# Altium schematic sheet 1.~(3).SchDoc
size 420 x 297 mm
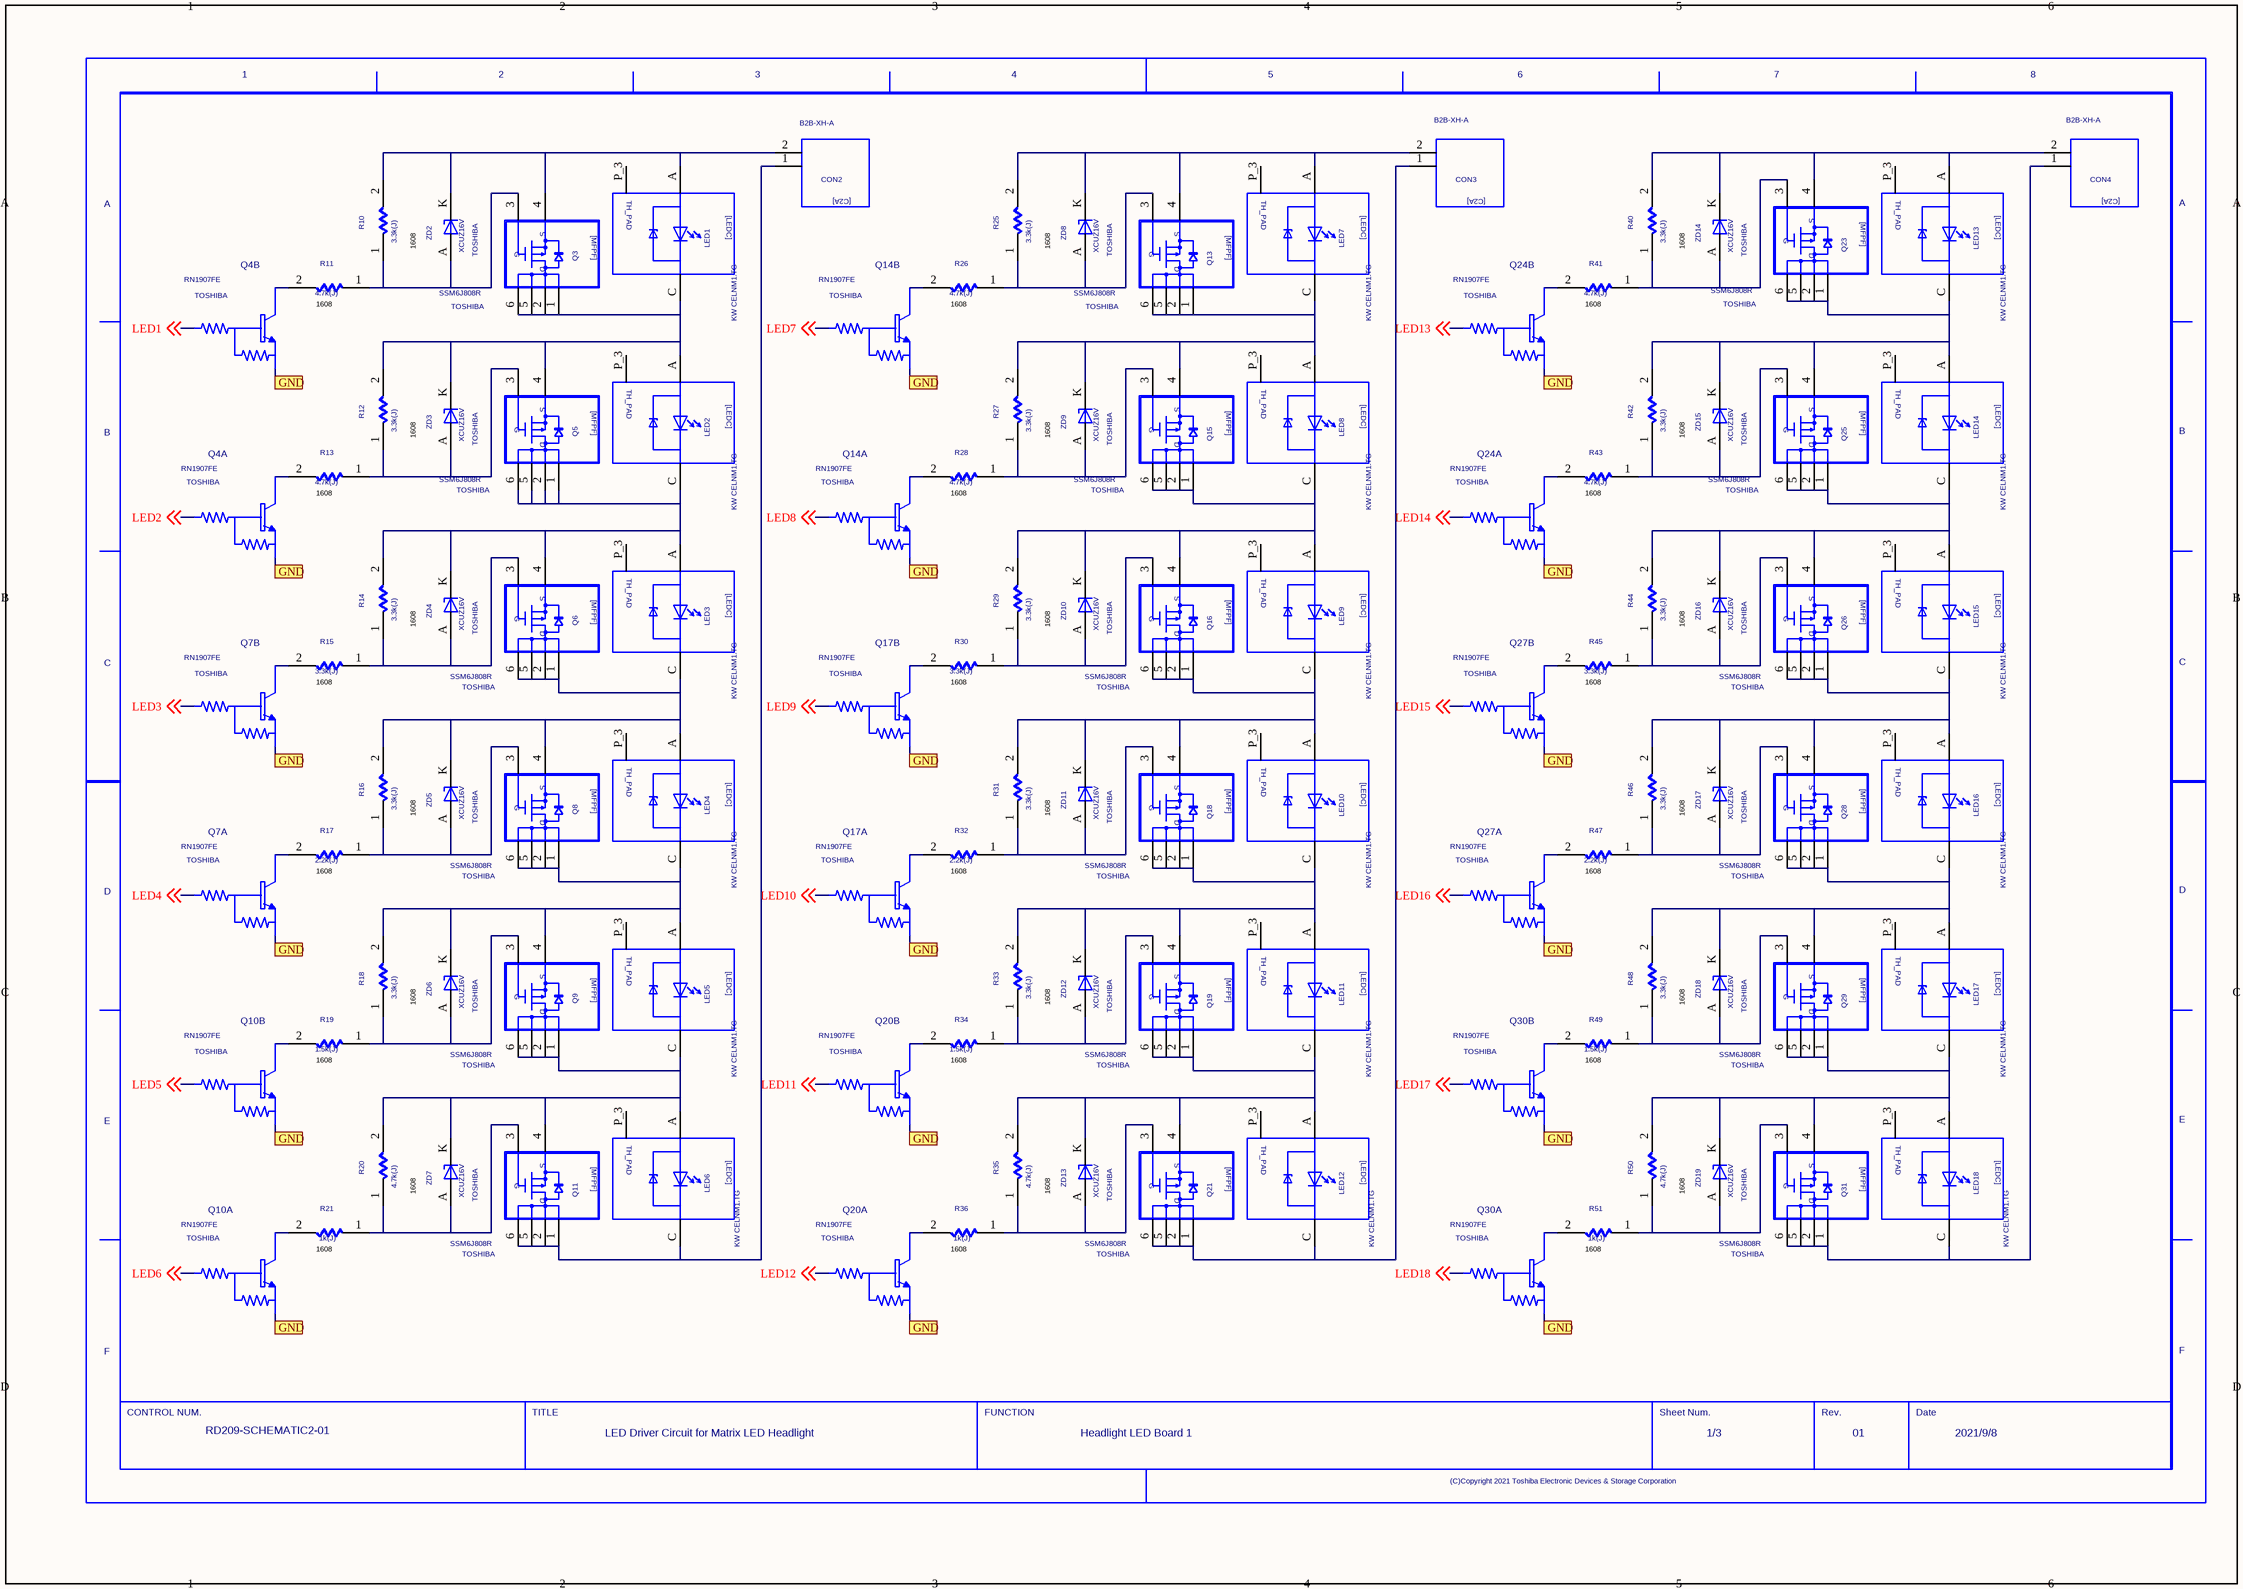
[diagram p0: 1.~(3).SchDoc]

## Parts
CON2  VAL3: B2B-XH-A  (hidden comment: C2A)
CON3  VAL3: B2B-XH-A  (hidden comment: C2A)
CON4  VAL3: B2B-XH-A  (hidden comment: C2A)
LED1  VAL3: KW CELNM1.TG  (hidden comment: LEDC)
LED2  VAL3: KW CELNM1.TG  (hidden comment: LEDC)
LED3  VAL3: KW CELNM1.TG  (hidden comment: LEDC)
LED4  VAL3: KW CELNM1.TG  (hidden comment: LEDC)
LED5  VAL3: KW CELNM1.TG  (hidden comment: LEDC)
LED6  VAL3: KW CELNM1.TG  (hidden comment: LEDC)
LED7  VAL3: KW CELNM1.TG  (hidden comment: LEDC)
LED8  VAL3: KW CELNM1.TG  (hidden comment: LEDC)
LED9  VAL3: KW CELNM1.TG  (hidden comment: LEDC)
LED10  VAL3: KW CELNM1.TG  (hidden comment: LEDC)
LED11  VAL3: KW CELNM1.TG  (hidden comment: LEDC)
LED12  VAL3: KW CELNM1.TG  (hidden comment: LEDC)
LED13  VAL3: KW CELNM1.TG  (hidden comment: LEDC)
LED14  VAL3: KW CELNM1.TG  (hidden comment: LEDC)
LED15  VAL3: KW CELNM1.TG  (hidden comment: LEDC)
LED16  VAL3: KW CELNM1.TG  (hidden comment: LEDC)
LED17  VAL3: KW CELNM1.TG  (hidden comment: LEDC)
LED18  VAL3: KW CELNM1.TG  (hidden comment: LEDC)
Q3  USERCOMPTEXT3: TOSHIBA  VAL3: SSM6J808R  (hidden comment: MFPF)
Q4  USERCOMPTEXT3: TOSHIBA  VAL3: RN1907FE  (hidden comment: RN1907FE_1)  (parts A,B of 2)
Q5  USERCOMPTEXT3: TOSHIBA  VAL3: SSM6J808R  (hidden comment: MFPF)
Q6  USERCOMPTEXT3: TOSHIBA  VAL3: SSM6J808R  (hidden comment: MFPF)
Q7  USERCOMPTEXT3: TOSHIBA  VAL3: RN1907FE  (hidden comment: RN1907FE_1)  (parts A,B of 2)
Q8  USERCOMPTEXT3: TOSHIBA  VAL3: SSM6J808R  (hidden comment: MFPF)
Q9  USERCOMPTEXT3: TOSHIBA  VAL3: SSM6J808R  (hidden comment: MFPF)
Q10  USERCOMPTEXT3: TOSHIBA  VAL3: RN1907FE  (hidden comment: RN1907FE_1)  (parts A,B of 2)
Q11  USERCOMPTEXT3: TOSHIBA  VAL3: SSM6J808R  (hidden comment: MFPF)
Q13  USERCOMPTEXT3: TOSHIBA  VAL3: SSM6J808R  (hidden comment: MFPF)
Q14  USERCOMPTEXT3: TOSHIBA  VAL3: RN1907FE  (hidden comment: RN1907FE_1)  (parts A,B of 2)
Q15  USERCOMPTEXT3: TOSHIBA  VAL3: SSM6J808R  (hidden comment: MFPF)
Q16  USERCOMPTEXT3: TOSHIBA  VAL3: SSM6J808R  (hidden comment: MFPF)
Q17  USERCOMPTEXT3: TOSHIBA  VAL3: RN1907FE  (hidden comment: RN1907FE_1)  (parts A,B of 2)
Q18  USERCOMPTEXT3: TOSHIBA  VAL3: SSM6J808R  (hidden comment: MFPF)
Q19  USERCOMPTEXT3: TOSHIBA  VAL3: SSM6J808R  (hidden comment: MFPF)
Q20  USERCOMPTEXT3: TOSHIBA  VAL3: RN1907FE  (hidden comment: RN1907FE_1)  (parts A,B of 2)
Q21  USERCOMPTEXT3: TOSHIBA  VAL3: SSM6J808R  (hidden comment: MFPF)
Q23  USERCOMPTEXT3: TOSHIBA  VAL3: SSM6J808R  (hidden comment: MFPF)
Q24  USERCOMPTEXT3: TOSHIBA  VAL3: RN1907FE  (hidden comment: RN1907FE_1)  (parts A,B of 2)
Q25  USERCOMPTEXT3: TOSHIBA  VAL3: SSM6J808R  (hidden comment: MFPF)
Q26  USERCOMPTEXT3: TOSHIBA  VAL3: SSM6J808R  (hidden comment: MFPF)
Q27  USERCOMPTEXT3: TOSHIBA  VAL3: RN1907FE  (hidden comment: RN1907FE_1)  (parts A,B of 2)
Q28  USERCOMPTEXT3: TOSHIBA  VAL3: SSM6J808R  (hidden comment: MFPF)
Q29  USERCOMPTEXT3: TOSHIBA  VAL3: SSM6J808R  (hidden comment: MFPF)
Q30  USERCOMPTEXT3: TOSHIBA  VAL3: RN1907FE  (hidden comment: RN1907FE_1)  (parts A,B of 2)
Q31  USERCOMPTEXT3: TOSHIBA  VAL3: SSM6J808R  (hidden comment: MFPF)
R10  VAL1: 3.3k(J)  (hidden comment: R)
R11  VAL1: 4.7k(J)  (hidden comment: R)
R12  VAL1: 3.3k(J)  (hidden comment: R)
R13  VAL1: 4.7k(J)  (hidden comment: R)
R14  VAL1: 3.3k(J)  (hidden comment: R)
R15  VAL1: 3.3k(J)  (hidden comment: R)
R16  VAL1: 3.3k(J)  (hidden comment: R)
R17  VAL1: 2.2k(J)  (hidden comment: R)
R18  VAL1: 3.3k(J)  (hidden comment: R)
R19  VAL1: 1.5k(J)  (hidden comment: R)
R20  VAL1: 4.7k(J)  (hidden comment: R)
R21  VAL1: 1k(J)  (hidden comment: R)
R25  VAL1: 3.3k(J)  (hidden comment: R)
R26  VAL1: 4.7k(J)  (hidden comment: R)
R27  VAL1: 3.3k(J)  (hidden comment: R)
R28  VAL1: 4.7k(J)  (hidden comment: R)
R29  VAL1: 3.3k(J)  (hidden comment: R)
R30  VAL1: 3.3k(J)  (hidden comment: R)
R31  VAL1: 3.3k(J)  (hidden comment: R)
R32  VAL1: 2.2k(J)  (hidden comment: R)
R33  VAL1: 3.3k(J)  (hidden comment: R)
R34  VAL1: 1.5k(J)  (hidden comment: R)
R35  VAL1: 4.7k(J)  (hidden comment: R)
R36  VAL1: 1k(J)  (hidden comment: R)
R40  VAL1: 3.3k(J)  (hidden comment: R)
R41  VAL1: 4.7k(J)  (hidden comment: R)
R42  VAL1: 3.3k(J)  (hidden comment: R)
R43  VAL1: 4.7k(J)  (hidden comment: R)
R44  VAL1: 3.3k(J)  (hidden comment: R)
R45  VAL1: 3.3k(J)  (hidden comment: R)
R46  VAL1: 3.3k(J)  (hidden comment: R)
R47  VAL1: 2.2k(J)  (hidden comment: R)
R48  VAL1: 3.3k(J)  (hidden comment: R)
R49  VAL1: 1.5k(J)  (hidden comment: R)
R50  VAL1: 4.7k(J)  (hidden comment: R)
R51  VAL1: 1k(J)  (hidden comment: R)
U?  DATE: 2021/9/8  REVISION: 01  SHEETNUMBER: 1/3  FUNCTION: Headlight LED Board 1  TITLE: LED Driver Circuit for / Matrix LED Headlight  DRAWINGNUMBER: RD209-SCHEMATIC2-01  (hidden comment: WAKU_DEF100)
ZD2  USERCOMPTEXT3: TOSHIBA  VAL3: XCUZ16V  (hidden comment: ZD)
ZD3  USERCOMPTEXT3: TOSHIBA  VAL3: XCUZ16V  (hidden comment: ZD)
ZD4  USERCOMPTEXT3: TOSHIBA  VAL3: XCUZ16V  (hidden comment: ZD)
ZD5  USERCOMPTEXT3: TOSHIBA  VAL3: XCUZ16V  (hidden comment: ZD)
ZD6  USERCOMPTEXT3: TOSHIBA  VAL3: XCUZ16V  (hidden comment: ZD)
ZD7  USERCOMPTEXT3: TOSHIBA  VAL3: XCUZ16V  (hidden comment: ZD)
ZD8  USERCOMPTEXT3: TOSHIBA  VAL3: XCUZ16V  (hidden comment: ZD)
ZD9  USERCOMPTEXT3: TOSHIBA  VAL3: XCUZ16V  (hidden comment: ZD)
ZD10  USERCOMPTEXT3: TOSHIBA  VAL3: XCUZ16V  (hidden comment: ZD)
ZD11  USERCOMPTEXT3: TOSHIBA  VAL3: XCUZ16V  (hidden comment: ZD)
ZD12  USERCOMPTEXT3: TOSHIBA  VAL3: XCUZ16V  (hidden comment: ZD)
ZD13  USERCOMPTEXT3: TOSHIBA  VAL3: XCUZ16V  (hidden comment: ZD)
ZD14  USERCOMPTEXT3: TOSHIBA  VAL3: XCUZ16V  (hidden comment: ZD)
ZD15  USERCOMPTEXT3: TOSHIBA  VAL3: XCUZ16V  (hidden comment: ZD)
ZD16  USERCOMPTEXT3: TOSHIBA  VAL3: XCUZ16V  (hidden comment: ZD)
ZD17  USERCOMPTEXT3: TOSHIBA  VAL3: XCUZ16V  (hidden comment: ZD)
ZD18  USERCOMPTEXT3: TOSHIBA  VAL3: XCUZ16V  (hidden comment: ZD)
ZD19  USERCOMPTEXT3: TOSHIBA  VAL3: XCUZ16V  (hidden comment: ZD)

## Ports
GND

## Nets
LED2: Q4.2 ; off-sheet LED2
LED3: Q7.5 ; off-sheet LED3
LED4: Q7.2 ; off-sheet LED4
LED5: Q10.5 ; off-sheet LED5
LED6: Q10.2 ; off-sheet LED6
LED7: Q14.5 ; off-sheet LED7
LED8: Q14.2 ; off-sheet LED8
LED9: Q17.5 ; off-sheet LED9
LED10: Q17.2 ; off-sheet LED10
LED11: Q20.5 ; off-sheet LED11
LED12: Q20.2 ; off-sheet LED12
LED13: Q24.5 ; off-sheet LED13
LED14: Q24.2 ; off-sheet LED14
LED15: Q27.5 ; off-sheet LED15
LED16: Q27.2 ; off-sheet LED16
LED17: Q30.5 ; off-sheet LED17
LED18: Q30.2 ; off-sheet LED18
LED+1: CON2.2 LED1.A Q3.4 R10.2 ZD2.K(C)
LED+2: CON3.2 LED7.A Q13.4 R25.2 ZD8.K(C)
LED+3: CON4.2 LED13.A Q23.4 R40.2 ZD14.K(C)
LED-1: CON2.1 LED6.C Q11.1 Q11.2 Q11.5 Q11.6
LED-2: CON3.1 LED12.C Q21.1 Q21.2 Q21.5 Q21.6
SIG1: Q4.5 ; off-sheet LED1  [also labelled LED1]
SIG2: Q4.3 R11.2
SIG3: Q3.3 R10.1 R11.1 ZD2.A
SIG6: Q5.3 R12.1 R13.1 ZD3.A
SIG7: Q4.6 R13.2
SIG10: Q7.6 R17.2
SIG11: Q8.3 R16.1 R17.1 ZD5.A
SIG12: Q4.1 Q4.4 Q7.1 Q7.4 Q10.1 Q10.4 Q14.1 Q14.4 Q17.1 Q17.4 Q20.1 Q20.4 Q24.1 Q24.4 Q27.1 Q27.4 Q30.1 Q30.4 ; port GND  [also labelled SIG18, SIG21, SIG26, SIG30, SIG34, SIG35, SIG40, SIG45, SIG51, SIG54, SIG59, SIG60, SIG66, SIG72, SIG74, SIG8]
SIG15: LED3.C LED4.A Q6.1 Q6.2 Q6.5 Q6.6 Q8.4 R16.2 ZD5.K(C)
SIG16: Q6.3 R14.1 R15.1 ZD4.A
SIG17: Q7.3 R15.2
SIG19: Q10.6 R21.2
SIG20: Q11.3 R20.1 R21.1 ZD7.A
SIG23: LED5.C LED6.A Q9.1 Q9.2 Q9.5 Q9.6 Q11.4 R20.2 ZD7.K(C)
SIG24: Q9.3 R18.1 R19.1 ZD6.A
SIG25: Q10.3 R19.2
SIG28: LED2.C LED3.A Q5.1 Q5.2 Q5.5 Q5.6 Q6.4 R14.2 ZD4.K(C)
SIG29: Q20.3 R34.2
SIG32: Q13.3 R25.1 R26.1 ZD8.A
SIG33: Q14.3 R26.2
SIG36: Q21.3 R35.1 R36.1 ZD13.A
SIG37: Q20.6 R36.2
SIG38: Q17.3 R30.2
SIG39: LED9.C LED10.A Q16.1 Q16.2 Q16.5 Q16.6 Q18.4 R31.2 ZD11.K(C)
SIG42: LED8.C LED9.A Q15.1 Q15.2 Q15.5 Q15.6 Q16.4 R29.2 ZD10.K(C)
SIG43: LED10.C LED11.A Q18.1 Q18.2 Q18.5 Q18.6 Q19.4 R33.2 ZD12.K(C)
SIG44: LED7.C LED8.A Q13.1 Q13.2 Q13.5 Q13.6 Q15.4 R27.2 ZD9.K(C)
SIG46: Q17.6 R32.2
SIG47: LED11.C LED12.A Q19.1 Q19.2 Q19.5 Q19.6 Q21.4 R35.2 ZD13.K(C)
SIG48: Q16.3 R29.1 R30.1 ZD10.A
SIG49: Q18.3 R31.1 R32.1 ZD11.A
SIG50: Q15.3 R27.1 R28.1 ZD9.A
SIG52: Q14.6 R28.2
SIG55: Q27.3 R45.2
SIG57: LED15.C LED16.A Q26.1 Q26.2 Q26.5 Q26.6 Q28.4 R46.2 ZD17.K(C)
SIG58: LED14.C LED15.A Q25.1 Q25.2 Q25.5 Q25.6 Q26.4 R44.2 ZD16.K(C)
SIG61: Q29.3 R48.1 R49.1 ZD18.A
SIG62: Q24.3 R41.2
SIG63: Q31.3 R50.1 R51.1 ZD19.A
SIG64: Q23.3 R40.1 R41.1 ZD14.A
SIG65: Q30.6 R51.2
SIG67: Q30.3 R49.2
SIG69: Q24.6 R43.2
SIG71: Q28.3 R46.1 R47.1 ZD17.A
SIG73: LED13.C LED14.A Q23.1 Q23.2 Q23.5 Q23.6 Q25.4 R42.2 ZD15.K(C)
SIG75: Q26.3 R44.1 R45.1 ZD16.A
SIG76: LED16.C LED17.A Q28.1 Q28.2 Q28.5 Q28.6 Q29.4 R48.2 ZD18.K(C)
SIG77: LED17.C LED18.A Q29.1 Q29.2 Q29.5 Q29.6 Q31.4 R50.2 ZD19.K(C)
SIG78: Q27.6 R47.2
SIG214: LED1.C LED2.A Q3.1 Q3.2 Q3.5 Q3.6 Q5.4 R12.2 ZD3.K(C)
SIG215: LED4.C LED5.A Q8.1 Q8.2 Q8.5 Q8.6 Q9.4 R18.2 ZD6.K(C)
SIG216: Q19.3 R33.1 R34.1 ZD12.A
SIG217: Q25.3 R42.1 R43.1 ZD15.A
SIG218: CON4.1 LED18.C Q31.1 Q31.2 Q31.5 Q31.6

Not connected (* = marked no-connect by the designer): LED1 P_3(NC); LED2 P_3(NC); LED3 P_3(NC); LED4 P_3(NC); LED5 P_3(NC); LED6 P_3(NC); LED7 P_3(NC); LED8 P_3(NC); LED9 P_3(NC); LED10 P_3(NC); LED11 P_3(NC); LED12 P_3(NC); LED13 P_3(NC); LED14 P_3(NC); LED15 P_3(NC); LED16 P_3(NC); LED17 P_3(NC); LED18 P_3(NC)

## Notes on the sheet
- 1608
- (near R11) 1608
- (near R26) 1608
- (near R41) 1608
- (near R13) 1608
- (near R28) 1608
- (near R43) 1608
- (near R15) 1608
- (near R30) 1608
- (near R45) 1608
- (near R17) 1608
- (near R32) 1608
- (near R47) 1608
- (near R19) 1608
- (near R34) 1608
- (near R49) 1608
- (near R21) 1608
- (near R36) 1608
- (near R51) 1608

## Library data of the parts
CON2-CON4 = C2A: SAVEAREA0: -4611,-206,24632,18258; SAVECOUNT: 25; TIME: 13:28:28; UPDATEUSER: tomizawa-y; UPDATETIME: 12:08:31; OriginalSymbolOrigin: (2540,15240)
LED1-LED18 = LEDC: SAVEAREA0: -10936,-329,35896,28705; TIME: 14:49:55; UPDATEUSER: fukuda-y; UPDATETIME: 15:53:51; SAVECOUNT: 15; OriginalSymbolOrigin: (5080,25400); COMPONENTNAME: LED; CDBNAME: KW
Q3 Q5 Q6 Q8 Q9 Q11 Q13 Q15 Q16 Q18 Q19 Q21 Q23 Q25 Q26 Q28 Q29 Q31 = MFPF: SAVECOUNT: 11; SAVEAREA0: -6011,0,28984,22860; OriginalSymbolOrigin: (5080,20320); COMPONENTNAME: TSOP6F
Q4 Q7 Q10 Q14 Q17 Q20 Q24 Q27 Q30 = RN1907FE_1: COMP: ES6; TIME: 08:46:53; UPDATEUSER: t5459927; UPDATETIME: 14:30:50; SAVECOUNT: 6; SAVEAREA0: -3836,-13019,18528,3377; OriginalSymbolOrigin: (0,5080); CaptureCellPackProp: RN1907FE_1A
R10 R19 R25 R34 R40 R49 = R: OriginalSymbolOrigin: (5080,5080); COMPONENTNAME: R0603_1; VAL2: 100mW
R11 R18 R26 R33 R41 R48 = R: OriginalSymbolOrigin: (5080,5080); COMPONENTNAME: R0603_2; VAL2: 100mW
R12 R27 R42 = R: OriginalSymbolOrigin: (5080,5080); VAL2: 100mW; COMPONENTNAME: R0603_3
R13 R15 R28 R30 R43 R45 = R: OriginalSymbolOrigin: (5080,5080); COMPONENTNAME: R0603_4; VAL2: 100mW
R14 R17 R29 R32 R44 R47 = R: OriginalSymbolOrigin: (5080,5080); COMPONENTNAME: R0603_5; VAL2: 100mW
R16 R31 R46 = R: OriginalSymbolOrigin: (5080,5080); VAL2: 100mW; COMPONENTNAME: R0603_6
R20 R35 R50 = R: OriginalSymbolOrigin: (5080,5080); VAL2: 100mW; COMPONENTNAME: R0603_7
R21 R36 R51 = R: OriginalSymbolOrigin: (5080,5080); COMPONENTNAME: R0603_8; VAL2: 100mW
U? = WAKU_DEF100: PLOTTIME: HH:MM; SAVEAREA0: 148187,-66180,486823,89919; TIME: 14:30:25; UPDATEUSER: t5459927; UPDATETIME: 14:28:22; SAVECOUNT: 6; OriginalSymbolOrigin: (10160,284480)
ZD2-ZD19 = ZD: SAVEAREA0: -4630,-153,17114,13055; TIME: 14:49:55; UPDATEUSER: fukuda-y; UPDATETIME: 08:18:42; SAVECOUNT: 6; OriginalSymbolOrigin: (5080,5080); COMPONENTNAME: USC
